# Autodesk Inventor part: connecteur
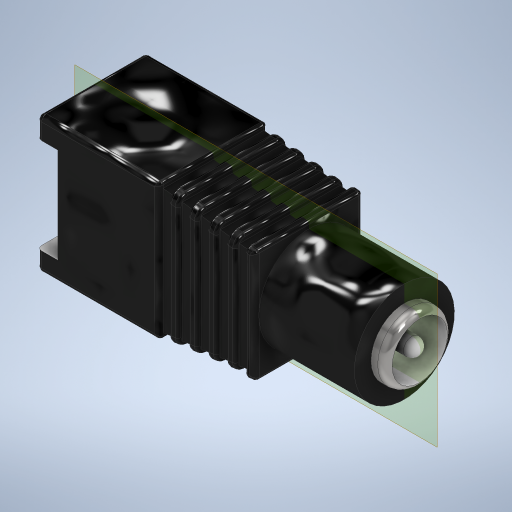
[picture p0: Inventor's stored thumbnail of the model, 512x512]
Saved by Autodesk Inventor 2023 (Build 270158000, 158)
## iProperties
Created: 2025-02
Part Number: connecteur
Material: Générique
Document SubType Name: Modeling
Designer: Buhl
Density: 1 g/cm^3
Appearance: Par défaut
Author: Buhl
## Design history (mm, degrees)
sketch "Esquisse1"
  geometry: C1 r 5.25 at (0, 0); 1 further point
  constraints: 1 centre point, 1 coincident
  dimensions: "d0" = 10.5 diameter of C1
extrude "Extrusion1" new body sketch "Esquisse1" distance "d1" = 10; taper "d2" = 0 deg
sketch "Esquisse2"
  geometry: C1 r 3.5 at (0, 0); 1 further point
  constraints: 1 centre point, 1 coincident
  dimensions: "d3" = 7 diameter of C1
extrude "Extrusion2" join sketch "Esquisse2" distance "d4" = 1.7; taper "d5" = 0 deg
fillet "Congé1" dims "d6" = 1
sketch "Esquisse3"
  geometry: C1 r 0.9 at (0, 0); C2 r 2.9 at (0, 0); 1 further point
  constraints: 2 centre point, 2 coincident
  dimensions: "d7" = 1.8 diameter of C1; "d8" = 5.8 diameter of C2
extrude "Extrusion3" cut sketch "Esquisse3" distance "d9" = 8; taper "d10" = 0 deg
fillet "Congé2" dims "d11" = 0.9
sketch "Esquisse4" dims "d25" = 10
  geometry: L1 (-10.3, -7.15)-(-22.8, -7.15); L2 (-22.8, -7.15)-(-22.8, 7.15); L3 (-22.8, 7.15)-(-10, 7.15); L4 (-10, 7.15)-(-10, -6.85); L5 (0, 0)-(-22.929, 0); L6 (0, -5.25)-(0, 5.25) reference; L7 (0, -5.635)-(0, 5.9); L8 (-0.263, -5.933)-(-0.663, -5.983); L9 (4.122, -4.78)-(-10, -6.545); L10 (-1, -5.685)-(-1, 9.302); L11 (-2, -7.15)-(-2, 9.302); L12 (-3, -5.935)-(-3, 9.302); L13 (-4, -7.15)-(-4, 9.302); L14 (-5, -6.185)-(-5, 9.302); L15 (-6, -7.15)-(-6, 9.302); L16 (-7, -6.435)-(-7, 9.302); L17 (-8, -7.15)-(-8, 9.302); L18 (-9, -6.685)-(-9, 9.302); L19 (-10, -7.15)-(-10, 9.302); L20 (-2.263, -6.183)-(-2.663, -6.233); L21 (-4.263, -6.433)-(-4.663, -6.483); L22 (-6.263, -6.683)-(-6.663, -6.733); L23 (-2, -5.545)-(-2, -5.885); L24 (-4, -5.795)-(-4, -6.135); L25 (-6, -6.045)-(-6, -6.385); L26 (-8, -6.295)-(-8, -6.635); L27 (-8.263, -6.933)-(-8.663, -6.983); A1 r 0.3 centre (-0.3, -5.635) between (-0.263, -5.933) and (0, -5.635); A2 r 0.3 centre (-0.7, -5.685) between (-1, -5.685) and (-0.663, -5.983); A3 r 0.3 centre (-2.7, -5.935) between (-3, -5.935) and (-2.663, -6.233); A4 r 0.3 centre (-4.7, -6.185) between (-5, -6.185) and (-4.663, -6.483); A5 r 0.3 centre (-6.7, -6.435) between (-7, -6.435) and (-6.663, -6.733); A6 r 0.3 centre (-4.3, -6.135) between (-4.263, -6.433) and (-4, -6.135); A7 r 0.3 centre (-2.3, -5.885) between (-2.263, -6.183) and (-2, -5.885); A8 r 0.3 centre (-6.3, -6.385) between (-6.263, -6.683) and (-6, -6.385); A9 r 0.3 centre (-8.3, -6.635) between (-8.263, -6.933) and (-8, -6.635); A10 r 0.3 centre (-8.7, -6.685) between (-9, -6.685) and (-8.663, -6.983); A11 r 0.3 centre (-10.3, -6.85) between (-10.3, -7.15) and (-10, -6.85); 26 further points
  constraints: 52 end point, 40 point on line, 22 point on circle, 22 tangent, 11 centre point, 8 equal radius, 3 collinear, 3 horizontal, 3 parallel, 2 midpoint, 2 vertical, 1 perpendicular, 27 other
  dimensions: "d12" = 14.3 distance of L1.end L2.end; "d13" = 12.8 distance of L2.end L3.end; "d14" = 7.15 distance between parallel lines of L3 L5; "d15" = 10 distance between parallel lines of L4 L6; "d16" = 11.8 distance of L7.end point (0, -5.9); "d17" = 5.9 distance from line of L7.end L5; "d18" = 0.6 distance from line of point (-0.463, -5.958) L9; "d19" = 1 distance between parallel lines of L10 L6; "d22" = 1 distance of point (-1, -7.15) L11.start; "d28" = 0.3 radius of A1 (derived); "d29" = 0.3 radius of A3 (derived); "d30" = 0.3 radius of A6 (derived)
extrude "Extrusion4" join sketch "Esquisse4" stored distance "d31" = 11.44; taper "d32" = 0 deg
mirror "Symétrie1"
sketch "Esquisse5"
  geometry: L1 (1, -5.72)-(1, 5.72) reference; L2 (1, -5.72)-(2, -5.72) reference; L3 (2, -5.72)-(2, 5.72) reference; L4 (2, 5.72)-(1, 5.72) reference; L5 (3, -5.72)-(3, 5.72) reference; L6 (3, -5.72)-(4, -5.72) reference; L7 (4, -5.72)-(4, 5.72) reference; L8 (4, 5.72)-(3, 5.72) reference; L9 (5, -5.72)-(5, 5.72) reference; L10 (5, -5.72)-(6, -5.72) reference; L11 (6, -5.72)-(6, 5.72) reference; L12 (6, 5.72)-(5, 5.72) reference; L13 (7, -5.72)-(7, 5.72) reference; L14 (7, -5.72)-(8, -5.72) reference; L15 (8, -5.72)-(8, 5.72) reference; L16 (8, 5.72)-(7, 5.72) reference; L17 (9, -5.72)-(9, 5.72) reference; L18 (9, -5.72)-(10, -5.72) reference; L19 (10, -5.72)-(10, 5.72) reference; L20 (10, 5.72)-(9, 5.72) reference; L21 (0, -5.72)-(0, 5.72) reference; L22 (0, -5.72)-(0.7, -5.72); L23 (1, 5.72)-(1, -5.72) reference; L24 (1, -5.27)-(2, -5.27); L25 (2, -5.72)-(2, 5.72) reference; L26 (3, -5.72)-(3, 5.72) reference; L27 (2.3, -5.72)-(2.7, -5.72); L28 (3, -5.42)-(3, -5.27); L29 (4, -5.72)-(4, 5.72) reference; L30 (4, -5.27)-(4, -5.42); L31 (5, -5.72)-(6, -5.72) reference; L32 (4.3, -5.72)-(4.7, -5.72); L33 (5, -5.42)-(5, -5.27); L34 (5, -5.72)-(5, 5.72) reference; L35 (6, -5.72)-(6, 5.72) reference; L36 (6, -5.27)-(6, -5.42); L37 (6.3, -5.72)-(6.7, -5.72); L38 (7, -5.42)-(7, -5.27); L39 (7, -5.72)-(7, 5.72) reference; L40 (8, -5.72)-(8, 5.72) reference; L41 (8, -5.27)-(8, -5.42); L42 (8.3, -5.72)-(8.7, -5.72); L43 (9, -5.72)-(9, 5.72) reference; L44 (9, -5.42)-(9, -5.27); L45 (2, -5.27)-(2, -5.42); L46 (2.263, -5.72)-(2.263, 5.72) reference; L47 (1, -5.27)-(1, -5.42); L48 (10, -5.72)-(10, 5.72) reference; L49 (10, -5.223)-(10, -5.72); L50 (10, -5.72)-(10.709, -5.72); L51 (10.709, -5.72)-(10.709, -6.88); L52 (10.709, -6.88)-(0, -6.88); L53 (0, -6.88)-(0, -5.72); L54 (9, -5.27)-(10, -5.27); L55 (7, -5.27)-(8, -5.27); L56 (5, -5.27)-(6, -5.27); L57 (3, -5.27)-(4, -5.27); L58 (-0.467, -5.27)-(0, -5.27); L59 (1, -5.27)-(2, -5.27); A1 r 0.3 centre (2.7, -5.42) between (2.7, -5.72) and (3, -5.42); A2 r 0.3 centre (4.3, -5.42) between (4, -5.42) and (4.3, -5.72); A3 r 0.3 centre (4.7, -5.42) between (4.7, -5.72) and (5, -5.42); A4 r 0.3 centre (6.3, -5.42) between (6, -5.42) and (6.3, -5.72); A5 r 0.3 centre (6.7, -5.42) between (6.7, -5.72) and (7, -5.42); A6 r 0.3 centre (8.3, -5.42) between (8, -5.42) and (8.3, -5.72); A7 r 0.3 centre (8.7, -5.42) between (8.7, -5.72) and (9, -5.42); A8 r 0.3 centre (2.3, -5.42) between (2, -5.42) and (2.3, -5.72); A9 r 0.3 centre (0.7, -5.42) between (0.7, -5.72) and (1, -5.42); 17 further points
  constraints: 52 end point, 31 point on line, 18 point on circle, 18 tangent, 9 centre point, 8 horizontal, 5 perpendicular, 3 collinear, 3 equal radius, 2 vertical, 1 parallel
  dimensions: "d34" = 0.3 radius of A1 (derived); "d35" = 0.3 radius of A2 (derived); "d36" = 0.3 radius of A6 (derived); "d37" = 0.3 radius of A7 (derived); "d38" = 0.3 radius of A8 (derived); "d39" = 0.3 radius of A9 (derived)
extrude "Extrusion5" cut sketch "Esquisse5" stored distance "d40" = 100; taper "d41" = 0 deg
mirror "Symétrie2"
fillet "Congé3" dims "d42" = 1
fillet "Congé4" dims "d43" = 0.5
fillet "Congé5" dims "d44" = 0.5
fillet "Congé6" dims "d45" = 0.5
sketch "Esquisse6"
  geometry: L1 (-9.54, 1.6)-(2.877, 1.6); L2 (2.877, 1.6)-(2.877, 11.6); L3 (2.877, 11.6)-(-9.54, 11.6); L4 (-9.54, 11.6)-(-9.54, 1.6); L5 (-10.94, 13.3)-(-10.94, 0) reference; L6 (0, 13.8)-(-10.44, 13.8) reference; 1 further point
  constraints: 8 end point, 2 parallel, 1 horizontal, 1 perpendicular
  dimensions: "d47" = 1.4 distance between parallel lines of L4 L5; "d48" = 10 distance of L1.end L2.end; "d49" = 2.2 distance between parallel lines of L6 L3
extrude "Extrusion6" cut sketch "Esquisse6" distance "d50" = 2.2; taper "d51" = 0 deg
node "Solide1"
node "Boucle projetée1"
node "Boucle projetée2"
node "Boucle projetée3"
node "Boucle projetée4"
node "Boucle projetée5"
node "Plan de construction1"
other parameters: "d33" = 0.45
